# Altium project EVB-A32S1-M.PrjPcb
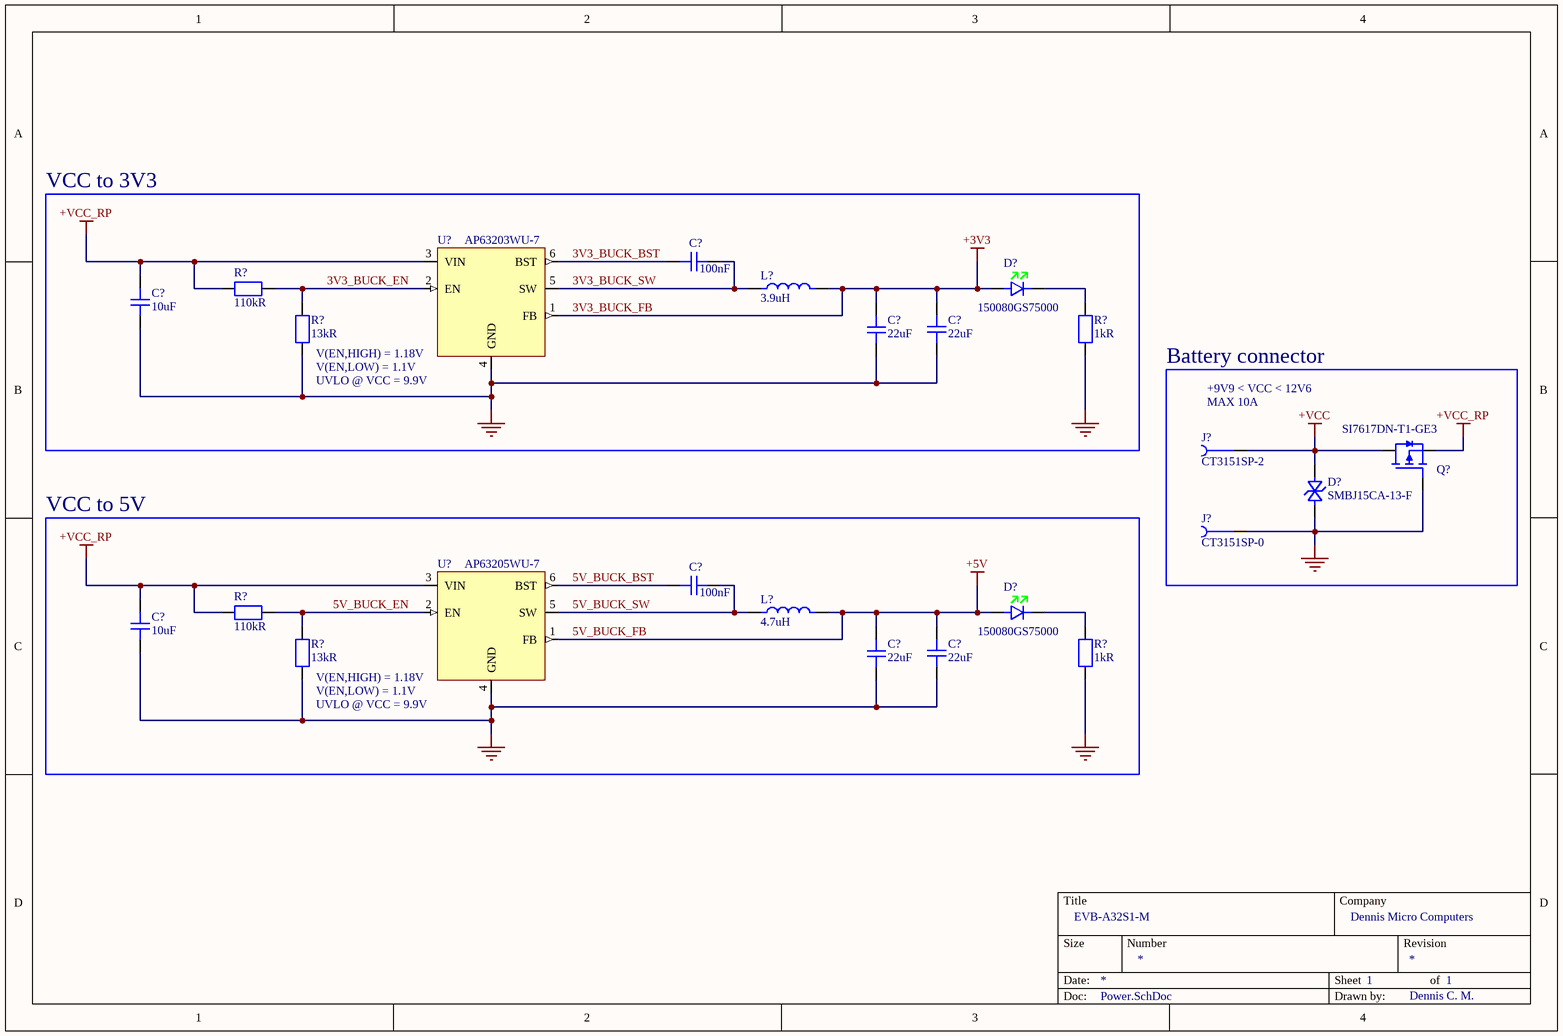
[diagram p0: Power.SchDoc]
CompanyName: Dennis Micro Computers; DrawnBy: Dennis C. M.; Title: EVB-A32S1-M
2 sheets, 24 parts. Net scope: global (net labels, ports and power ports of the same name join across sheets).
Sheets:
  Power.SchDoc
  MCU.SchDoc

## Sheet Power.SchDoc: EVB-A32S1-M
size A4; SheetNumber: 1; SheetTotal: 1

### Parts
(Parts that share a designator on the sheet are numbered #1, #2 ... from top to bottom, then left to right.)
C?#1  value 100nF  [CAP_0402_A]  (hidden comment: CC0402MRX5R6BB104)
C?#2  value 10uF  [CAP_0805_A]  (hidden comment: CC0805KRX5R7BB106)
C?#3  value 22uF  [CAP_0805_A]  (hidden comment: CC0805MKX5R6BB226)
C?#4  value 22uF  [CAP_0805_A]  (hidden comment: CC0805MKX5R6BB226)
C?#5  value 100nF  [CAP_0402_A]  (hidden comment: CC0402MRX5R6BB104)
C?#6  value 10uF  [CAP_0805_A]  (hidden comment: CC0805KRX5R7BB106)
C?#7  value 22uF  [CAP_0805_A]  (hidden comment: CC0805MKX5R6BB226)
C?#8  value 22uF  [CAP_0805_A]  (hidden comment: CC0805MKX5R6BB226)
D?#1  150080GS75000  [150080GS75000]
D?#2  SMBJ15CA-13-F  [D_TVS_BI_SMB_DO-214AA]
D?#3  150080GS75000  [150080GS75000]
J?#1  CT3151SP-2  [CT3151SP-2]
J?#2  CT3151SP-0  [CT3151SP-0]
L?#1  value 3.9uH  [1255AY-XXXX=P3-Footprint-1]  (hidden comment: 1255AY-3R9N=P3)
L?#2  value 4.7uH  [1255AY-XXXX=P3-Footprint-1]  (hidden comment: 1255AY-4R7M=P3)
Q?  SI7617DN-T1-GE3  [POWERPACK-1212-8]
R?#1  value 110kR  [RES_0402_A]  (hidden comment: RC0402FR-07110KL)
R?#2  value 13kR  [RES_0402_A]  (hidden comment: RC0402FR-0713KL)
R?#3  value 1kR  [RES_0402_A]  (hidden comment: RC0402FR-071KL)
R?#4  value 110kR  [RES_0402_A]  (hidden comment: RC0402FR-07110KL)
R?#5  value 13kR  [RES_0402_A]  (hidden comment: RC0402FR-0713KL)
R?#6  value 1kR  [RES_0402_A]  (hidden comment: RC0402FR-071KL)
U?#1  AP63203WU-7  [TSOT-23-6]
U?#2  AP63205WU-7  [TSOT-23-6]

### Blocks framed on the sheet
VCC to 3V3: C?#1-C?#4 D?#1 L?#1 R?#1-R?#3 U?#1
Battery connector: D?#2 J?#1 J?#2 Q?
VCC to 5V: C?#5-C?#8 D?#3 L?#2 R?#4-R?#6 U?#2

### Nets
3V3_BUCK_FB: C?#3.2 C?#4.2 D?#1.1 L?#1.2 U?#1.1(FB)  [also labelled +3V3]
5V_BUCK_FB: C?#7.2 C?#8.2 D?#3.1 L?#2.2 U?#2.1(FB)  [also labelled +5V]
+VCC: D?#2.1 J?#1.1 Q?.1(D)
+VCC_RP: C?#2.2 C?#6.2 Q?.3(S) R?#1.2 R?#4.2 U?#1.3(VIN) U?#2.3(VIN)
GND: C?#2.1 C?#3.1 C?#4.1 C?#6.1 C?#7.1 C?#8.1 D?#2.2 J?#2.1 Q?.2(G) R?#2.1 R?#3.1 R?#5.1 R?#6.1 U?#1.4(GND) U?#2.4(GND)
3V3_BUCK_BST: C?#1.2 U?#1.6(BST)
3V3_BUCK_EN: R?#1.1 R?#2.2 U?#1.2(EN)
3V3_BUCK_SW: C?#1.1 L?#1.1 U?#1.5(SW)
5V_BUCK_BST: C?#5.2 U?#2.6(BST)
5V_BUCK_EN: R?#4.1 R?#5.2 U?#2.2(EN)
5V_BUCK_SW: C?#5.1 L?#2.1 U?#2.5(SW)
NetD?#1_2: D?#1.2 R?#3.2
NetD?#3_2: D?#3.2 R?#6.2

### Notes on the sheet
- V(EN,HIGH) = 1.18V
- V(EN,LOW) = 1.1V
- UVLO @ VCC = 9.9V
- +9V9 < VCC < 12V6
- (near J?#1) MAX 10A

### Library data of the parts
C?#1 C?#5 = CMP-001-00009-5: Multilayer Ceramic Capacitor, 0.1 uF, 25 V, ± 20%, X7R, 0402 [1005 Metric]; Dielectric: X5R; Temperature Coefficient: 30ppm/°C; Voltage Rating: 10V
C?#2 C?#6 = CMP-001-00018-1: 0805 10 uF 16 V ±10% Tolerance X5R Multilayer Ceramic Chip Capacitor; Voltage Rating (DC): 16V
C?#3 C?#4 C?#7 C?#8 = CMP-001-00014-3: Multilayer Ceramic Capacitor, 22 uF, 10 V, ± 20%, X5R, 0805 [2012 Metric]; Voltage Rating (DC): 10V
D?#1 D?#3 = CMP-007-00000-3: WURTH ELEKTRONIK - 150080GS75000 - LED, Green, SMD, 0805, 30 mA, 3.2 V, 520 nm; Forward Current: 30mA; Forward Voltage: 3.2V; Luminous Intensity: 450mcd; Max Reverse Voltage (DC): 5V; Lens Transparency: Clear; Power Dissipation: 105mW; Lens Style: Clear,Flat,Rectangular; Lens Size: 1.25mm; Viewing Angle: 140°; Test Current: 20mA; Dominant Wavelength: 520nm; Lens Color: Colorless
D?#2 = CMP-004-00000-1: Tvs Diode, Bidir, 15V, 600W, Do-214Aa Rohs Compliant: Yes; Max Reverse Leakage Current: 5uA; Reverse Breakdown Voltage: 16.7V; Breakdown Voltage: 19.2V; Clamping Voltage: 24.4V; Power Line Protection: No; Max Surge Current: 24A; Number of Bidirectional Channels: 1; Test Current: 1mA; Value: 280pF; Polarity: Bidirectional; Diode Type: ZENER
J?#1 = CMP-002-00001-2: Conn 4mm Safety Banana Jack F 1 POS Solder RA Thru-Hole 1 Port Bag; pin to pad: 1>1+2+3+4; Body Material: Nylon,Polyamide,PA66; Insulation: Mating End Insulated; Gender: Female
J?#2 = CMP-002-00000-4: Conn 4mm Safety Banana Jack F 1 POS Solder RA Thru-Hole 1 Port Bag; pin to pad: 1>1+2+3+4; Body Material: Nylon,Polyamide,PA66; Insulation: Mating End Insulated; Gender: Female
L?#1 = CMP-006-00002-1: Inductor Power Shielded Wirewound 3.9uH 30% 100KHz Ferrite 4.2A 0.0264Ohm DCR 2424 T/R; DC Resistance (DCR): 26.4mR; Saturation Current: 4.7A
L?#2 = CMP-006-00001-4: Inductor Power Shielded Wirewound 4.7uH 20% 100KHz Ferrite 4A 0.0276Ohm DCR 2424 T/R; DC Resistance (DCR): 27.6mR; Current Rating: 4.5A
Q? = CMP-00000-2: P CHANNEL MOSFET, -30V, 35A; Transistor; Transistor Polarity: P Channel; Continuous Drain Current Id: -35A; Source; pin to pad: 1>5+6+7+8 2>4 3>1+2+3; Rise Time: 43ns; Drain to Source Resistance: 12.3mR; Turn-Off Delay Time: 30ns; Turn-On Delay Time: 40ns; Threshold Voltage: -2.5V; Max Power Dissipation: 52W; Fall Time: 11ns; Power Dissipation: 3.7W; Polarity: P-CHANNEL; Number of Elements: 1; Input Capacitance: 1.8nF; Gate to Source Voltage (Vgs): 25V
R?#1 R?#4 = CMP-009-00000-5: SMD Chip Resistor, 110 kOhm, ± 1%, 63 mW, 0402 [1005 Metric], Thick Film, General Purpose; Max Power Dissipation: 63mW; Voltage Rating (DC): 50V; Temperature Coefficient: 100ppm/°C
R?#2 R?#5 = CMP-009-00001-5: SMD Chip Resistor, 13 kOhm, ± 1%, 63 mW, 0402 [1005 Metric], Thick Film, General Purpose; Temperature Coefficient: 100ppm/°C; Voltage Rating: 50V; Max Power Dissipation: 63mW; Power Rating: 62.5mW
R?#3 R?#6 = CMP-009-00002-5: SMD Chip Resistor, 1 kOhm, ± 1%, 62.5 mW, 0402 [1005 Metric], Thick Film, General Purpose; Temperature Coefficient: 100ppm/°C; Voltage Rating (AC): 50V; Power Rating: 62.5mW; Max Power Dissipation: 63mW
U?#1 = CMP-019-00004-4: AP63203 Series 3.3 V 2 A SMT Fixed Low IQ Synchronous Buck - TSOT-26; Max Duty Cycle: 100%; Output Voltage: 3.3V; Number of Outputs: 1; Max Supply Voltage: 32V; Switching Frequency: 1.1MHz; Min Supply Voltage: 3.8V; Nominal Supply Current: 22uA; Output Current: 2A
U?#2 = CMP-019-00003-4: AP63205 Series 32 V 2 A 1.1 MHz Synchronous Buck Converter -TSOT-26; Number of Outputs: 1; Max Duty Cycle: 100%; Output Current: 2A; Switching Frequency: 1.1MHz; Max Supply Voltage: 32V; Output Voltage: 5V; Nominal Supply Current: 22uA; Min Supply Voltage: 3.8V

## Sheet MCU.SchDoc: EVB-A32S1-M
size A4; SheetNumber: 2; SheetTotal: 2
